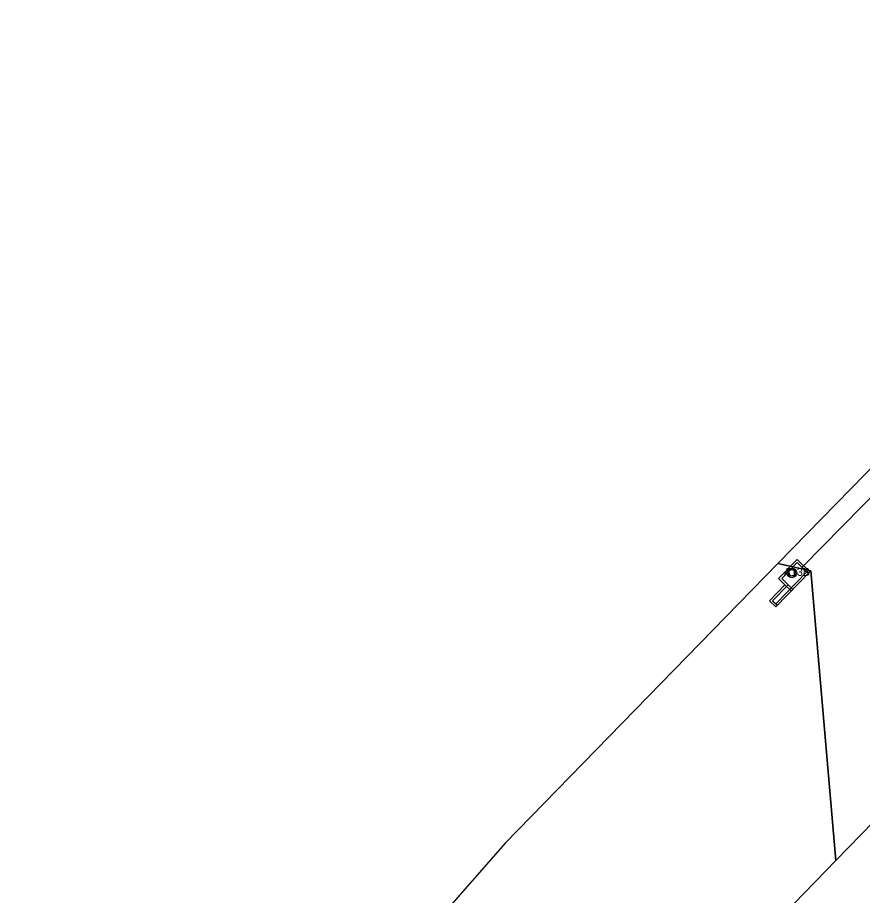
# Model space of a CAD drawing. Extents: x 2252703 to 2264864, y 13787568 to 13790989.
# Drawn here: x 2252703.1 to 2252893, y 13788691.8 to 13788889.2 of the extents above; entities that cross this region are included whole.
import ezdxf

# ---------------------------------------------------------------- set-up
doc = ezdxf.new("R2010")
doc.units = 0
for name, color, linetype in [('D_DRAIN_MISC', 7, 'Continuous'), ('D_DRAIN_NOTES_1', 7, 'Continuous'), ('D_DRN_AREA_X', 7, 'Continuous'), ('D_INLET_1', 7, 'Continuous'), ('D_PIPES_1', 7, 'Continuous')]:
    doc.layers.add(name, color=color, linetype=linetype)

msp = doc.modelspace()

# ---------------------------------------------------------------- linework, layer by layer
at = {"layer": 'D_DRAIN_MISC'}
for p, q in [((2252879.46, 13788765.62), (2252879.46, 13788765.62)), ((2252876.64, 13788764.88), (2252876.64, 13788764.88)), ((2252877.72, 13788763.83), (2252877.72, 13788763.83)), ((2252875.97, 13788762.04), (2252875.97, 13788762.04)), ((2252878.79, 13788762.79), (2252878.79, 13788762.79))]:
    msp.add_line(p, q, dxfattribs=at)
at = {"layer": 'D_DRN_AREA_X'}
for p, q in [((2252874.02, 13788766.49), (2252812.73, 13788703.57)), ((2252812.73, 13788703.57), (2252703.12, 13788578.79)), ((2252812.73, 13788703.57), (2252812.73, 13788703.57))]:
    msp.add_line(p, q, dxfattribs=at)
for points in [[(2253012.64, 13788889.21), (2252992.46, 13788869.19), (2252988.07, 13788865.34), (2252984.21, 13788862.61), (2252965.2, 13788853.73), (2252958.91, 13788850.5), (2252955.35, 13788848.13), (2252952.47, 13788845.86), (2252945.11, 13788838.75), (2252942.89, 13788836.53), (2252939.85, 13788833.54), (2252938.06, 13788831.83), (2252935.45, 13788829.22), (2252929.84, 13788823.59), (2252874.02, 13788766.49), (2252881.47, 13788764.79), (2252887.1, 13788699.7), (2252903.98, 13788717.11)], [(2252887.1, 13788699.7), (2252881.47, 13788764.79), (2252874.02, 13788766.49)], [(2252874.02, 13788766.49), (2252874.02, 13788766.49)], [(2252733.51, 13788549.52), (2252804.45, 13788622.34), (2252848.93, 13788668), (2252863.44, 13788675.31), (2252887.1, 13788699.7)]]:
    msp.add_lwpolyline(points, dxfattribs=at)
at = {"layer": 'D_INLET_1'}
for p, q in [((2252874.19, 13788763.08), (2252878.38, 13788767.38)), ((2252878.38, 13788767.38), (2252881.24, 13788764.59)), ((2252874.9, 13788763.09), (2252878.39, 13788766.67)), ((2252878.39, 13788766.67), (2252880.89, 13788764.23)), ((2252873.56, 13788757.41), (2252880.54, 13788764.58)), ((2252873.57, 13788756.71), (2252881.24, 13788764.59)), ((2252872.14, 13788758.1), (2252875.62, 13788761.68)), ((2252872.84, 13788758.11), (2252876.33, 13788761.69)), ((2252874.19, 13788763.08), (2252875.62, 13788761.68)), ((2252874.9, 13788763.09), (2252877.41, 13788760.65)), ((2252875.62, 13788761.68), (2252877.06, 13788760.29)), ((2252872.14, 13788758.1), (2252873.57, 13788756.71)), ((2252872.84, 13788758.11), (2252873.92, 13788757.07))]:
    msp.add_line(p, q, dxfattribs=at)
for radius in [1.08, 0.75]:
    msp.add_circle((2252877.18, 13788764.36), radius, dxfattribs=at)
at = {"layer": 'D_PIPES_1'}
msp.add_line((2252879.46, 13788765.62), (2252942.99, 13788830.28), dxfattribs=at)

# ---------------------------------------------------------------- texts
at = {"layer": 'D_DRAIN_NOTES_1'}
msp.add_text('A13B', height=1.8, dxfattribs=at).set_placement((2252875.36, 13788763.69))

doc.saveas('drawing.dxf')
